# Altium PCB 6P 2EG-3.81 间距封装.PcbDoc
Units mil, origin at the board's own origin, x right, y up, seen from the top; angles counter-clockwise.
Board outline 6000 x 4000 mil, 2 copper layers (Top Layer, Bottom Layer); 1 components, 0 nets, 6 pads, 0 vias.
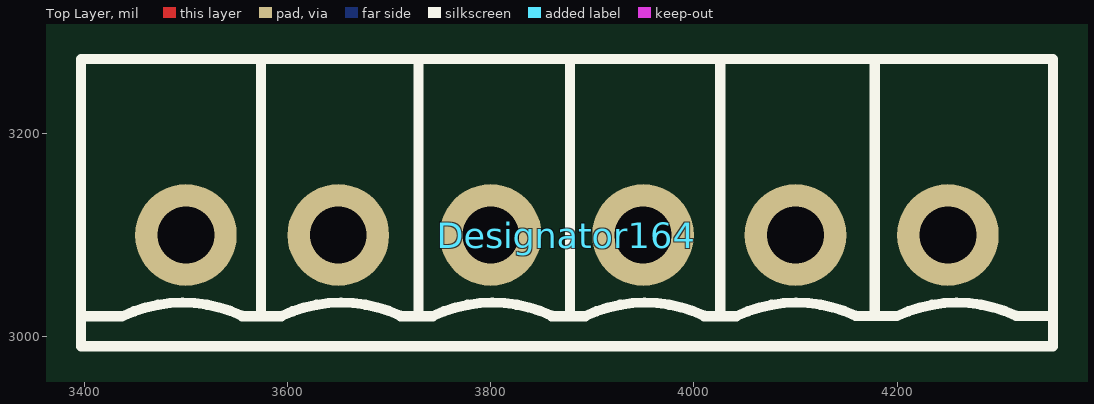
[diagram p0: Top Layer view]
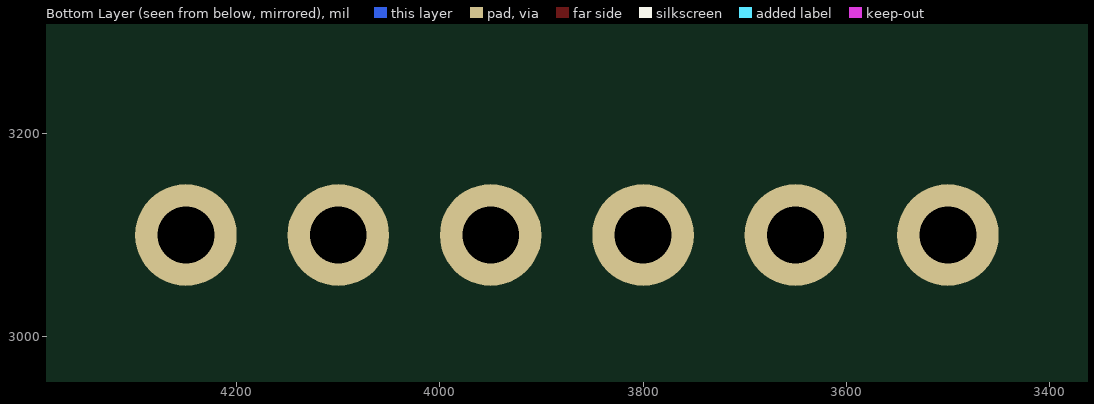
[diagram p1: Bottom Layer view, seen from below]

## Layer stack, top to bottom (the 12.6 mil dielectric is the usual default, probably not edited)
Top Solder: solder mask 0.4, Solder Resist, Dk 3.5
Top Layer: signal copper 1.4
Dielectric 1: dielectric 12.6, FR-4, Dk 4.8
Bottom Layer: signal copper 1.4
Bottom Solder: solder mask 0.4, Solder Resist, Dk 3.5

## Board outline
1000,1000 7000,1000 7000,5000 1000,5000

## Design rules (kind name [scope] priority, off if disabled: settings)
Clearance [All] p1: gap=10
PolygonConnect [All] p1: connectstyle=Relief reliefconductorwidth=10 reliefentries=4 polygonreliefangle="90 Angle" airgapwidth=10
RoutingVias [All] p1: holewidth=28 width=50 viastyle="Through Hole" minholewidth=28 minwidth=50 maxholewidth=28 maxwidth=50
SolderMaskExpansion [All] p1: expansion=4
Width [All] p1: maxlimit=10 minlimit=10 preferedwidth=10
30 further rules are at their usual default settings.

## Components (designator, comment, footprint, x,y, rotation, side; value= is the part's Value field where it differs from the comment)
Designator164 "Comment" CON3.81-6DA 3875,3100 r0 top

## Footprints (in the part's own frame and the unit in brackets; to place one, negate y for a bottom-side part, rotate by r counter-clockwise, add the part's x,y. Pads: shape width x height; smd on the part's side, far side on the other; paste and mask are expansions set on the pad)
CON3.81-6DA [mil]
  round 100 hole 56: 1(-375,0) 2(-225,0) 3(-75,0) 4(75,0) 5(225,0) 6(375,0)
  silkscreen extent -478,-109 478,173

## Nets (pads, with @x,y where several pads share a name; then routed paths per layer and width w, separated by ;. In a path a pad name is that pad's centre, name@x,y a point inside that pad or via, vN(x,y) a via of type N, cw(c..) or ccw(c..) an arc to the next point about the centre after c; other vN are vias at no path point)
pads on no net: Designator164.1 Designator164.2 Designator164.3 Designator164.4 Designator164.5 Designator164.6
